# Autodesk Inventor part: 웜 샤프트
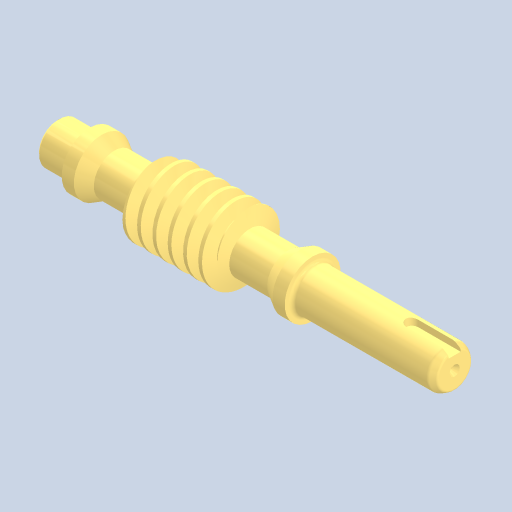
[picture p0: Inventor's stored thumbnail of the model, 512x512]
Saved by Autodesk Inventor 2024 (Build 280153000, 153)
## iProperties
Created: 2026-01
Part Number: 웜 샤프트
Material: 강철, 합금
Document SubType Name: Modeling
Designer: 2-10
Density: 7.73 g/cm^3
Appearance: 기본값
Author: jhkim
Sending System: Autodesk Inventor 2026
Preprocessor: ST-DEVELOPER v20.1
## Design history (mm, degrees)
feature "솔리드1"
node "솔리드2"
